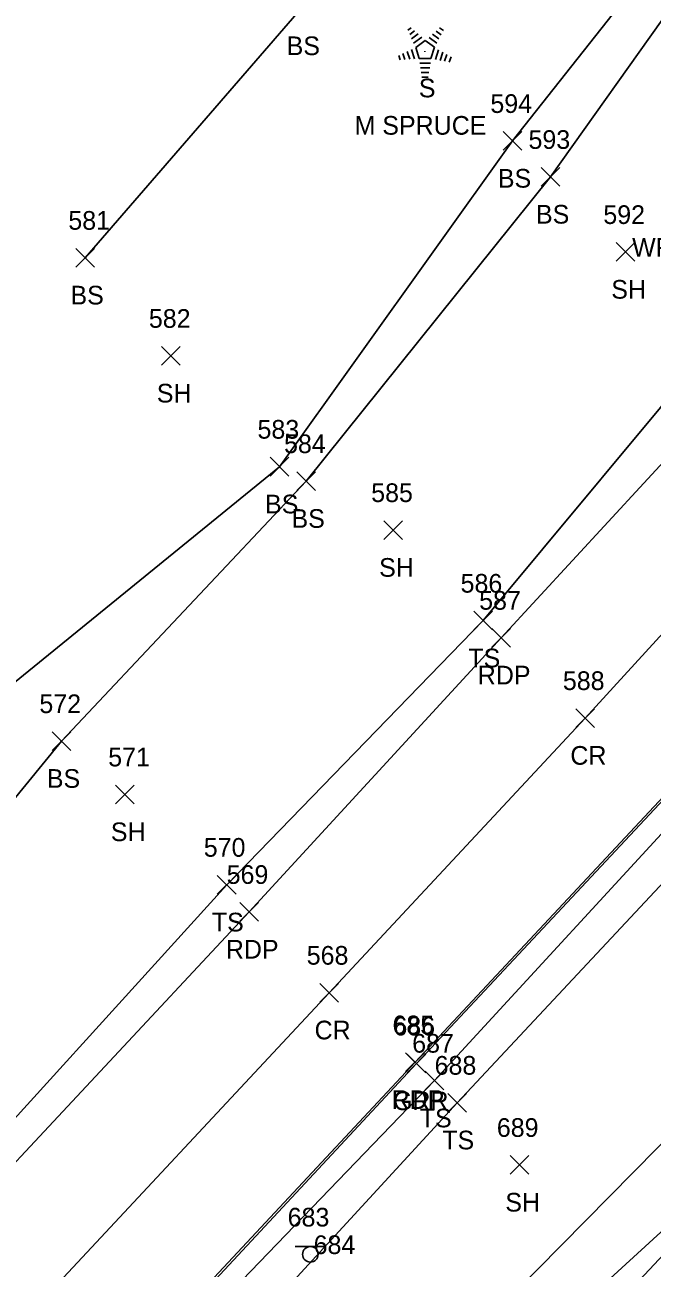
# Model space of a CAD drawing. Extents: x 1688195 to 1692013, y 424605 to 441234.
# Drawn here: x 1691519.2 to 1691586.4, y 439041.4 to 439174.5 of the extents above; entities that cross this region are included whole.
import ezdxf

# ---------------------------------------------------------------- set-up
doc = ezdxf.new("R2010")
doc.units = 0
for name, color, linetype in [('L_A', 7, 'Continuous'), ('L_C', 7, 'Continuous'), ('L_I', 7, 'Continuous'), ('L_TIC', 7, 'Continuous'), ('LELB', 7, 'Continuous'), ('LFNC', 7, 'Continuous'), ('LTC', 7, 'Continuous'), ('P_A', 7, 'Continuous'), ('P_I', 7, 'Continuous'), ('P_TIC', 7, 'Continuous'), ('PET', 7, 'Continuous'), ('PRC', 7, 'Continuous'), ('R_A', 7, 'Continuous'), ('R_I', 7, 'Continuous'), ('R_TIC', 7, 'Continuous'), ('RGR', 7, 'Continuous'), ('S_C', 7, 'Continuous'), ('S_I', 7, 'Continuous'), ('SSGN', 7, 'Continuous')]:
    doc.layers.add(name, color=color, linetype=linetype)

msp = doc.modelspace()

# ---------------------------------------------------------------- linework, layer by layer
at = {"layer": 'L_TIC'}
for points in [[(1691570.44, 439161.09), (1691572.44, 439163.09)], [(1691572.44, 439161.09), (1691570.44, 439163.09)], [(1691574.52, 439157.24), (1691576.52, 439159.24)], [(1691576.52, 439157.24), (1691574.52, 439159.24)], [(1691524.69, 439148.58), (1691526.69, 439150.58)], [(1691526.69, 439148.58), (1691524.69, 439150.58)], [(1691582.53, 439149.2), (1691584.53, 439151.2)], [(1691584.53, 439149.2), (1691582.53, 439151.2)], [(1691533.88, 439138.08), (1691535.88, 439140.08)], [(1691535.88, 439138.08), (1691533.88, 439140.08)], [(1691545.52, 439126.21), (1691547.52, 439128.21)], [(1691547.52, 439126.21), (1691545.52, 439128.21)], [(1691548.35, 439124.66), (1691550.35, 439126.66)], [(1691550.35, 439124.66), (1691548.35, 439126.66)], [(1691557.68, 439119.42), (1691559.68, 439121.42)], [(1691559.68, 439119.42), (1691557.68, 439121.42)], [(1691567.31, 439109.72), (1691569.31, 439111.72)], [(1691569.31, 439109.72), (1691567.31, 439111.72)], [(1691522.16, 439096.82), (1691524.16, 439098.82)], [(1691524.16, 439096.82), (1691522.16, 439098.82)], [(1691528.96, 439091.11), (1691530.96, 439093.11)], [(1691530.96, 439091.11), (1691528.96, 439093.11)], [(1691539.85, 439081.44), (1691541.85, 439083.44)], [(1691541.85, 439081.44), (1691539.85, 439083.44)], [(1691562.11, 439060.46), (1691564.11, 439062.46)], [(1691564.11, 439060.46), (1691562.11, 439062.46)], [(1691564.52, 439058.1), (1691566.52, 439060.1)], [(1691566.52, 439058.1), (1691564.52, 439060.1)], [(1691571.19, 439051.44), (1691573.19, 439053.44)], [(1691573.19, 439051.44), (1691571.19, 439053.44)]]:
    msp.add_lwpolyline(points, dxfattribs=at)
at = {"layer": 'LELB'}
for points in [[(1691372.73, 438902.64), (1691398.57, 438929.63), (1691421.61, 438954.81), (1691450.5, 438984.08), (1691477.46, 439013.34), (1691508.26, 439046.52), (1691540.85, 439082.44), (1691568.31, 439110.72), (1691593.69, 439141.21), (1691622.93, 439171.73), (1691652.84, 439206.76), (1691674.71, 439229.19), (1691701.22, 439256.48), (1691710.89, 439279.75), (1691723.95, 439307.99), (1691712.17, 439332.07), (1691693.94, 439358.26), (1691684, 439373.02)], [(1691525.69, 439149.58), (1691548.83, 439176.28), (1691571.85, 439208.37), (1691601.9, 439243.82), (1691616.58, 439266.33), (1691638.43, 439302.46), (1691663.4, 439335.24), (1691663.94, 439360.51)], [(1691358.65, 438915.95), (1691383.88, 438942.54), (1691406.19, 438968.83), (1691432.09, 439000.43), (1691458.78, 439030.79), (1691488.91, 439063.66), (1691516.55, 439102.83), (1691546.52, 439127.21), (1691571.44, 439162.09), (1691585.36, 439179.75), (1691595.61, 439189.84), (1691598.8, 439192.56), (1691623.09, 439224.33), (1691645.87, 439250.99)], [(1691362.51, 438912.64), (1691386.93, 438940.67), (1691409.23, 438967.09), (1691436.47, 438996.99), (1691463, 439026.81), (1691492.43, 439060.22), (1691523.16, 439097.82), (1691549.35, 439125.66), (1691575.52, 439158.24), (1691588.61, 439176.65), (1691597.67, 439188.52), (1691599.59, 439192.01), (1691624.28, 439223.08), (1691646.72, 439249.94), (1691645.87, 439250.99)], [(1691494.97, 438989.23), (1691529.39, 439026.47), (1691563.11, 439061.46), (1691592.32, 439093.25), (1691622.45, 439123.57), (1691640.28, 439144.55), (1691642.63, 439146.18), (1691644.54, 439148.64), (1691657.14, 439160.25), (1691677.5, 439185.53), (1691687.79, 439198.06), (1691700.53, 439206.6), (1691711.71, 439214.4), (1691729.93, 439221), (1691765.22, 439228.65), (1691785.8, 439230.06)], [(1691867.08, 439165.21), (1691844.95, 439160.27), (1691798.84, 439152.11), (1691745.51, 439147.11), (1691728.71, 439142.4), (1691709.09, 439133.88), (1691683, 439117.2), (1691643.28, 439091.08), (1691604.89, 439061.29), (1691572.53, 439026.72), (1691542.38, 438995.55), (1691505.84, 438957.5), (1691487.66, 438936.34), (1691466.81, 438915.54), (1691436.02, 438880.86), (1691415.55, 438858.76)], [(1691497.62, 438986.55), (1691532.48, 439023.13), (1691565.52, 439059.1), (1691594.4, 439089.96), (1691624.94, 439121.84), (1691642.24, 439143.61)], [(1691604.89, 439061.29), (1691570.2, 439029.58), (1691540.68, 438997.55), (1691504.19, 438958.83), (1691485.94, 438937.8), (1691466.29, 438916.24), (1691434.59, 438882.45), (1691414.01, 438860.1)]]:
    msp.add_lwpolyline(points, dxfattribs=at)
at = {"layer": 'LFNC'}
msp.add_lwpolyline([(1691844.63, 439219.19), (1691827.3, 439208.18), (1691808.98, 439197.07), (1691805.18, 439194.78), (1691802.65, 439193.15), (1691780.93, 439179.95), (1691740.49, 439155.55), (1691707.63, 439134.9), (1691682.09, 439120.04), (1691638.96, 439093.47), (1691599.84, 439067.34), (1691566.38, 439033.38), (1691536.95, 439001.22), (1691500.89, 438961.26), (1691462.91, 438919.55), (1691429.39, 438883.14), (1691411.26, 438863.12)], dxfattribs=at)
at = {"layer": 'LTC'}
for p, q in [((1691560.23, 439173.97), (1691560.59, 439174.22)), ((1691563.63, 439174.21), (1691564.05, 439173.9)), ((1691560.44, 439173.5), (1691560.97, 439173.89)), ((1691560.65, 439173.04), (1691561.36, 439173.55)), ((1691560.86, 439172.57), (1691561.74, 439173.21)), ((1691561.09, 439172.11), (1691562.1, 439172.85)), ((1691562.1, 439172.85), (1691563.1, 439172.12)), ((1691562.52, 439173.16), (1691563.33, 439172.57)), ((1691562.89, 439173.51), (1691563.57, 439173.02)), ((1691563.26, 439173.86), (1691563.81, 439173.46)), ((1691559.72, 439171.46), (1691559.93, 439170.81)), ((1691560.18, 439171.68), (1691560.45, 439170.84)), ((1691560.63, 439171.9), (1691560.96, 439170.88)), ((1691561.09, 439172.11), (1691561.47, 439170.92)), ((1691563.1, 439172.12), (1691562.7, 439170.92)), ((1691563.53, 439171.85), (1691563.19, 439170.81)), ((1691563.98, 439171.6), (1691563.69, 439170.72)), ((1691559.27, 439171.25), (1691559.42, 439170.78)), ((1691562.7, 439170.92), (1691561.47, 439170.92)), ((1691562.67, 439170.42), (1691561.52, 439170.42)), ((1691564.42, 439171.35), (1691564.18, 439170.62)), ((1691564.87, 439171.1), (1691564.68, 439170.53)), ((1691562.58, 439169.92), (1691561.59, 439169.92)), ((1691562.5, 439169.42), (1691561.67, 439169.42)), ((1691562.41, 439168.92), (1691561.74, 439168.92))]:
    msp.add_line(p, q, dxfattribs=at)
at = {"layer": 'P_TIC'}
for points in [[(1691569.24, 439107.89), (1691571.24, 439109.89)], [(1691571.24, 439107.89), (1691569.24, 439109.89)], [(1691578.21, 439099.29), (1691580.21, 439101.29)], [(1691580.21, 439099.29), (1691578.21, 439101.29)], [(1691542.27, 439078.53), (1691544.27, 439080.53)], [(1691544.27, 439078.53), (1691542.27, 439080.53)], [(1691550.83, 439069.88), (1691552.83, 439071.88)], [(1691552.83, 439069.88), (1691550.83, 439071.88)], [(1691560.01, 439062.43), (1691562.01, 439064.43)], [(1691562.01, 439062.43), (1691560.01, 439064.43)]]:
    msp.add_lwpolyline(points, dxfattribs=at)
at = {"layer": 'PET'}
for points in [[(1691375.46, 438899.9), (1691401.5, 438927.23), (1691424.19, 438951.44), (1691479.53, 439011.25), (1691510.32, 439044.28), (1691543.27, 439079.53), (1691570.24, 439108.89), (1691596.97, 439137.86), (1691630.02, 439173.34), (1691657.32, 439202.46), (1691678.85, 439225.99), (1691705.09, 439253.29), (1691720.65, 439270.18), (1691741.75, 439292.31), (1691750.04, 439301.33), (1691750.82, 439305.81), (1691750.97, 439309.53)], [(1691527.98, 439028.02), (1691561.01, 439063.43), (1691590.68, 439095.16), (1691619.98, 439126.48), (1691638.57, 439146.32), (1691653.83, 439162.94), (1691673.33, 439185.49), (1691673.65, 439189.01), (1691685.04, 439200.74), (1691697.53, 439210.68), (1691709.71, 439218.34), (1691715.71, 439221.67), (1691737.08, 439230.06)]]:
    msp.add_lwpolyline(points, dxfattribs=at)
at = {"layer": 'PRC'}
msp.add_lwpolyline([(1691383.45, 438891.46), (1691410.11, 438918.45), (1691432.71, 438943.44), (1691460.69, 438973.59), (1691487.77, 439002.58), (1691519.39, 439036.11), (1691551.83, 439070.88), (1691579.21, 439100.29), (1691605.82, 439129.37), (1691637.88, 439164.38), (1691665.6, 439193.96), (1691687.96, 439216.92), (1691714.01, 439245.27), (1691730.35, 439261.96), (1691750.53, 439284.62), (1691763.38, 439297.71)], dxfattribs=at)
at = {"layer": 'R_TIC'}
for points in [[(1691560.17, 439062.3), (1691562.17, 439064.3)], [(1691562.17, 439062.3), (1691560.17, 439064.3)]]:
    msp.add_lwpolyline(points, dxfattribs=at)
at = {"layer": 'RGR'}
msp.add_lwpolyline([(1691392.43, 438882.91), (1691415.63, 438907.66), (1691443.42, 438937.01), (1691473.56, 438969.15), (1691494.4, 438991.79), (1691528.19, 439027.86), (1691561.17, 439063.3), (1691590.77, 439094.95), (1691620.16, 439126.42), (1691638.64, 439146.14), (1691654.09, 439162.7)], dxfattribs=at)
at = {"layer": 'SSGN'}
for p, q in [((1691548.17, 439043.69), (1691551.5, 439043.69)), ((1691549.81, 439042.86), (1691549.81, 439042.86))]:
    msp.add_line(p, q, dxfattribs=at)
msp.add_circle((1691549.81, 439042.86), 0.833, dxfattribs=at)

# ---------------------------------------------------------------- texts
at = {"layer": 'L_A'}
for s, p in [('BS', (1691547.27, 439171.28)), ('S', (1691561.42, 439166.76)), ('BS', (1691569.88, 439157.09)), ('BS', (1691573.96, 439153.24)), ('BS', (1691524.13, 439144.58)), ('SH', (1691582.02, 439145.2)), ('SH', (1691533.37, 439134.08)), ('BS', (1691544.96, 439122.21)), ('BS', (1691547.79, 439120.66)), ('SH', (1691557.17, 439115.42)), ('TS', (1691566.72, 439105.72)), ('BS', (1691521.6, 439092.82)), ('SH', (1691528.45, 439087.11)), ('TS', (1691539.26, 439077.44)), ('TS', (1691561.52, 439056.46)), ('TS', (1691563.93, 439054.1)), ('SH', (1691570.68, 439047.44))]:
    msp.add_text(s, height=2, dxfattribs=at).set_placement(p)
at = {"layer": 'L_C'}
msp.add_text('M SPRUCE', height=2, dxfattribs=at).set_placement((1691554.54, 439162.76))
at = {"layer": 'L_I'}
for s, p in [('594', (1691569.08, 439165.09)), ('593', (1691573.16, 439161.24)), ('581', (1691523.9, 439152.58)), ('592', (1691581.17, 439153.2)), ('582', (1691532.52, 439142.08)), ('583', (1691544.15, 439130.21)), ('584', (1691546.99, 439128.66)), ('585', (1691556.32, 439123.42)), ('586', (1691565.89, 439113.72)), ('572', (1691520.8, 439100.82)), ('571', (1691528.17, 439095.11)), ('570', (1691538.4, 439085.44)), ('687', (1691560.71, 439064.46)), ('688', (1691563.11, 439062.1)), ('689', (1691569.77, 439055.44))]:
    msp.add_text(s, height=2, dxfattribs=at).set_placement(p)
at = {"layer": 'LTC'}
msp.add_text('.', height=1.04, rotation=270, dxfattribs=at).set_placement((1691561.98, 439171.86))
at = {"layer": 'P_A'}
for s, p in [('RDP', (1691567.73, 439103.89)), ('CR', (1691577.64, 439095.29)), ('RDP', (1691540.76, 439074.53)), ('CR', (1691550.26, 439065.88)), ('RDP', (1691558.5, 439058.43))]:
    msp.add_text(s, height=2, dxfattribs=at).set_placement(p)
at = {"layer": 'P_I'}
for s, p in [('587', (1691567.88, 439111.89)), ('588', (1691576.84, 439103.29)), ('569', (1691540.85, 439082.53)), ('568', (1691549.42, 439073.88)), ('685', (1691558.6, 439066.43))]:
    msp.add_text(s, height=2, dxfattribs=at).set_placement(p)
at = {"layer": 'R_A'}
msp.add_text('GRR', height=2, dxfattribs=at).set_placement((1691558.65, 439058.3))
at = {"layer": 'R_I'}
msp.add_text('686', height=2, dxfattribs=at).set_placement((1691558.7, 439066.3))
at = {"layer": 'S_C'}
msp.add_text('WRONG WAY & NO HITCHHIKING', height=2, dxfattribs=at).set_placement((1691584.25, 439149.7))
at = {"layer": 'S_I'}
for s, p in [('683', (1691547.38, 439045.84)), ('684', (1691550.16, 439042.89))]:
    msp.add_text(s, height=2, dxfattribs=at).set_placement(p)

doc.saveas('drawing.dxf')
